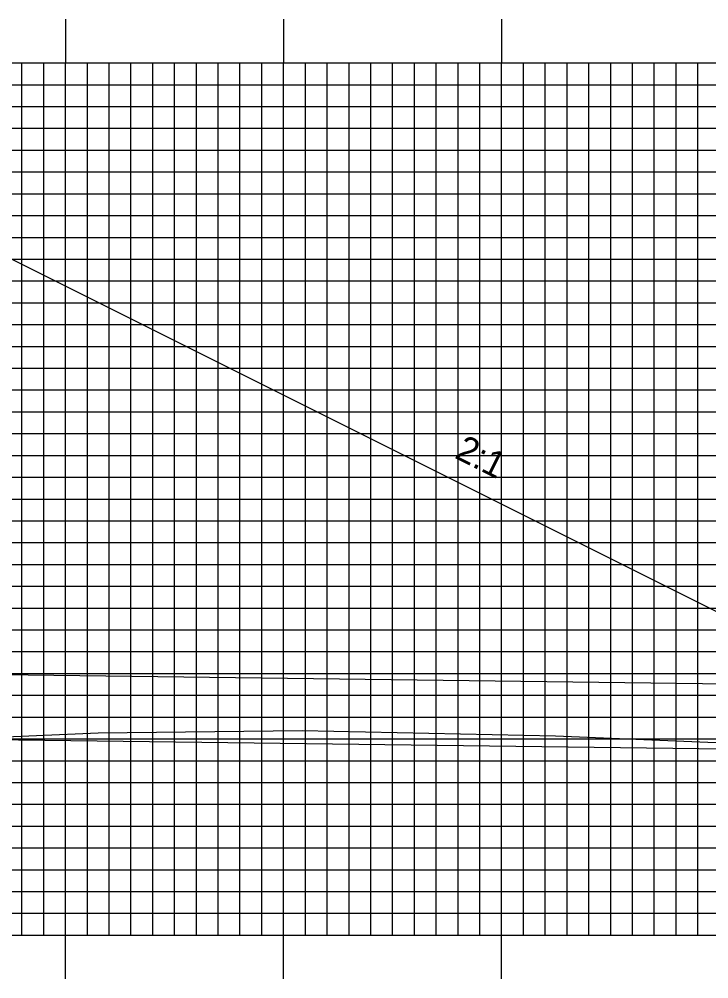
# Model space of a CAD drawing. Extents: x 1786189 to 1786532, y 442591 to 442811.
# Drawn here: x 1786382.44 to 1786414.06, y 442736.66 to 442780.67 of the extents above; entities that cross this region are included whole.
import ezdxf

# ---------------------------------------------------------------- set-up
doc = ezdxf.new("R2010")
doc.units = 0
for name, color, linetype in [('ANNOTATION', 7, 'Continuous'), ('D_Drainage_Culvert', 7, 'Continuous'), ('D_Roadway_Centerline', 7, 'Continuous'), ('D_Roadway_SlopeLines', 7, 'Continuous'), ('MAJOR', 7, 'Continuous'), ('MINOR', 7, 'Continuous'), ('S_Roadway_Centerline', 7, 'Continuous')]:
    doc.layers.add(name, color=color, linetype=linetype)

msp = doc.modelspace()

# ---------------------------------------------------------------- linework, layer by layer
at = {"layer": 'D_Drainage_Culvert'}
msp.add_lwpolyline([(1786286.414, 442748.831), (1786286.453, 442751.841), (1786430.441, 442749.997), (1786430.402, 442746.987)], close=True, dxfattribs=at)
at = {"layer": 'D_Roadway_Centerline'}
msp.add_lwpolyline([(1786286.773, 442749.01), (1786326.749, 442768.998), (1786331.565, 442771.406), (1786334.565, 442771.526), (1786342.565, 442771.846), (1786354.565, 442772.11), (1786366.565, 442772.374), (1786374.565, 442772.054), (1786377.565, 442771.934), (1786382.315, 442769.559), (1786427.289, 442747.072)], dxfattribs=at)
at = {"layer": 'D_Roadway_SlopeLines'}
msp.add_lwpolyline([(1786377.565, 442771.934), (1786427.289, 442747.072)], dxfattribs=at)
at = {"layer": 'MAJOR'}
for p, q in [((1786384.565, 442780.669), (1786384.565, 442778.665)), ((1786394.565, 442780.669), (1786394.565, 442778.665)), ((1786404.565, 442780.669), (1786404.565, 442778.665)), ((1786214.565, 442778.665), (1786494.565, 442778.665)), ((1786214.565, 442778.665), (1786494.565, 442778.665)), ((1786384.565, 442738.665), (1786384.565, 442778.665)), ((1786394.565, 442738.665), (1786394.565, 442778.665)), ((1786404.565, 442738.665), (1786404.565, 442778.665)), ((1786214.565, 442773.665), (1786494.565, 442773.665)), ((1786214.565, 442768.665), (1786494.565, 442768.665)), ((1786214.565, 442763.665), (1786494.565, 442763.665)), ((1786214.565, 442758.665), (1786494.565, 442758.665)), ((1786214.565, 442753.665), (1786494.565, 442753.665)), ((1786214.565, 442748.665), (1786494.565, 442748.665)), ((1786214.565, 442743.665), (1786494.565, 442743.665)), ((1786214.565, 442738.665), (1786494.565, 442738.665)), ((1786214.565, 442738.665), (1786494.565, 442738.665)), ((1786384.565, 442736.661), (1786384.565, 442738.665)), ((1786394.565, 442736.661), (1786394.565, 442738.665)), ((1786404.565, 442736.661), (1786404.565, 442738.665))]:
    msp.add_line(p, q, dxfattribs=at)
at = {"layer": 'MINOR'}
for p, q in [((1786382.565, 442738.665), (1786382.565, 442778.665)), ((1786383.565, 442738.665), (1786383.565, 442778.665)), ((1786385.565, 442738.665), (1786385.565, 442778.665)), ((1786386.565, 442738.665), (1786386.565, 442778.665)), ((1786387.565, 442738.665), (1786387.565, 442778.665)), ((1786388.565, 442738.665), (1786388.565, 442778.665)), ((1786389.565, 442738.665), (1786389.565, 442778.665)), ((1786390.565, 442738.665), (1786390.565, 442778.665)), ((1786391.565, 442738.665), (1786391.565, 442778.665)), ((1786392.565, 442738.665), (1786392.565, 442778.665)), ((1786393.565, 442738.665), (1786393.565, 442778.665)), ((1786395.565, 442738.665), (1786395.565, 442778.665)), ((1786396.565, 442738.665), (1786396.565, 442778.665)), ((1786397.565, 442738.665), (1786397.565, 442778.665)), ((1786398.565, 442738.665), (1786398.565, 442778.665)), ((1786399.565, 442738.665), (1786399.565, 442778.665)), ((1786400.565, 442738.665), (1786400.565, 442778.665)), ((1786401.565, 442738.665), (1786401.565, 442778.665)), ((1786402.565, 442738.665), (1786402.565, 442778.665)), ((1786403.565, 442738.665), (1786403.565, 442778.665)), ((1786405.565, 442738.665), (1786405.565, 442778.665)), ((1786406.565, 442738.665), (1786406.565, 442778.665)), ((1786407.565, 442738.665), (1786407.565, 442778.665)), ((1786408.565, 442738.665), (1786408.565, 442778.665)), ((1786409.565, 442738.665), (1786409.565, 442778.665)), ((1786410.565, 442738.665), (1786410.565, 442778.665)), ((1786411.565, 442738.665), (1786411.565, 442778.665)), ((1786412.565, 442738.665), (1786412.565, 442778.665)), ((1786413.565, 442738.665), (1786413.565, 442778.665)), ((1786214.565, 442777.665), (1786494.565, 442777.665)), ((1786214.565, 442776.665), (1786494.565, 442776.665)), ((1786214.565, 442775.665), (1786494.565, 442775.665)), ((1786214.565, 442774.665), (1786494.565, 442774.665)), ((1786214.565, 442772.665), (1786494.565, 442772.665)), ((1786214.565, 442771.665), (1786494.565, 442771.665)), ((1786214.565, 442770.665), (1786494.565, 442770.665)), ((1786214.565, 442769.665), (1786494.565, 442769.665)), ((1786214.565, 442767.665), (1786494.565, 442767.665)), ((1786214.565, 442766.665), (1786494.565, 442766.665)), ((1786214.565, 442765.665), (1786494.565, 442765.665)), ((1786214.565, 442764.665), (1786494.565, 442764.665)), ((1786214.565, 442762.665), (1786494.565, 442762.665)), ((1786214.565, 442761.665), (1786494.565, 442761.665)), ((1786214.565, 442760.665), (1786494.565, 442760.665)), ((1786214.565, 442759.665), (1786494.565, 442759.665)), ((1786214.565, 442757.665), (1786494.565, 442757.665)), ((1786214.565, 442756.665), (1786494.565, 442756.665)), ((1786214.565, 442755.665), (1786494.565, 442755.665)), ((1786214.565, 442754.665), (1786494.565, 442754.665)), ((1786214.565, 442752.665), (1786494.565, 442752.665)), ((1786214.565, 442751.665), (1786494.565, 442751.665)), ((1786214.565, 442750.665), (1786494.565, 442750.665)), ((1786214.565, 442749.665), (1786494.565, 442749.665)), ((1786214.565, 442747.665), (1786494.565, 442747.665)), ((1786214.565, 442746.665), (1786494.565, 442746.665)), ((1786214.565, 442745.665), (1786494.565, 442745.665)), ((1786214.565, 442744.665), (1786494.565, 442744.665)), ((1786214.565, 442742.665), (1786494.565, 442742.665)), ((1786214.565, 442741.665), (1786494.565, 442741.665)), ((1786214.565, 442740.665), (1786494.565, 442740.665)), ((1786214.565, 442739.665), (1786494.565, 442739.665))]:
    msp.add_line(p, q, dxfattribs=at)
at = {"layer": 'S_Roadway_Centerline'}
msp.add_lwpolyline([(1786315.332, 442748.759), (1786319.67, 442748.522), (1786327.559, 442748.265), (1786332.667, 442748.024), (1786346.24, 442748.033), (1786350.329, 442748.233), (1786353.553, 442747.967), (1786366.51, 442747.383), (1786374.73, 442747.456), (1786386.058, 442747.945), (1786395.413, 442748.051), (1786407.028, 442747.806), (1786414.013, 442747.513), (1786420.121, 442747.281), (1786428.367, 442747.041), (1786432.417, 442746.933), (1786435.537, 442747.122), (1786456.69, 442747.169), (1786456.783, 442747.164), (1786457.052, 442747.165), (1786476.091, 442747.114), (1786483.098, 442746.93), (1786494.565, 442746.743)], dxfattribs=at)

# ---------------------------------------------------------------- texts
at = {"layer": 'ANNOTATION'}
msp.add_text('2:1', height=1.2, rotation=333.4349, dxfattribs=at).set_placement((1786402.361, 442760.572))

doc.saveas('drawing.dxf')
